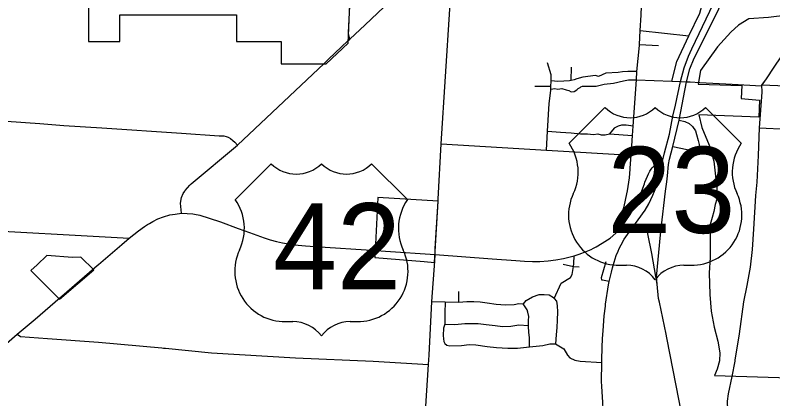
# Model space of a CAD drawing. Extents: x 1729596 to 1925846, y 659247 to 911751.
# Drawn here: x 1799698 to 1811952, y 827504 to 833706 of the extents above; entities that cross this region are included whole.
import ezdxf

# ---------------------------------------------------------------- set-up
doc = ezdxf.new("R2010")
doc.units = 0
for name, color, linetype in [('GM_X_City_Street', 7, 'Continuous'), ('GM_X_Corporation', 7, 'Continuous'), ('GM_X_County_Road', 7, 'Continuous'), ('GM_X_Township_Road', 7, 'Continuous'), ('GM_X_US_Route', 7, 'Continuous'), ('GM_X_US_Shield', 7, 'Continuous')]:
    doc.layers.add(name, color=color, linetype=linetype)

msp = doc.modelspace()

# ---------------------------------------------------------------- linework, layer by layer
at = {"layer": 'GM_X_City_Street'}
for points in [[(1810317, 832639), (1810397, 832959), (1810594, 833371), (1810771, 833738), (1810817, 833894), (1810835, 834363), (1810894, 835206), (1810935, 835731), (1810971, 836241), (1810972, 836258)], [(1809820, 833706), (1809822, 833736), (1809864, 834413), (1809877, 834634), (1809916, 835275), (1809958, 835900), (1809966, 836004), (1809968, 836028), (1809972, 836063)], [(1810558, 832630), (1810609, 832836), (1810677, 833010), (1810904, 833460), (1811253, 834162), (1811728, 835119), (1811786, 835192), (1811850, 835258), (1811945, 835287)], [(1805078, 833290), (1805108, 833319), (1805356, 833551), (1805763, 833930), (1806341, 834474), (1806704, 834818), (1806800, 834898), (1806981, 834892), (1807110, 834884), (1807396, 834863), (1807615, 834857), (1807685, 834849), (1807777, 834831), (1808186, 834806), (1808431, 834743), (1809378, 834672), (1809877, 834634)], [(1806587, 831627), (1806800, 834898)], [(1809670, 831595), (1809681, 831762), (1809691, 831914), (1809749, 832662), (1809755, 832796), (1809793, 833217), (1809794, 833230), (1809804, 833457), (1809820, 833706)], [(1809804, 833457), (1810594, 833371)], [(1809794, 833230), (1810103, 833214)], [(1802546, 830982), (1802546, 830982), (1803292, 831607), (1804693, 832927), (1804742, 832975), (1804765, 832997)], [(1808363, 832536), (1808364, 832559), (1808367, 832634), (1808367, 832642), (1808366, 832740), (1808308, 832933)], [(1808690, 832650), (1808696, 832864)], [(1809755, 832796), (1809609, 832796), (1809520, 832790), (1809449, 832781), (1809253, 832770), (1809131, 832716), (1809086, 832731), (1808880, 832706), (1808780, 832675), (1808737, 832660), (1808690, 832650), (1808661, 832644), (1808569, 832637), (1808475, 832636), (1808367, 832642)], [(1808362, 832511), (1808424, 832523), (1808474, 832510), (1808538, 832518), (1808608, 832499), (1808654, 832486), (1808691, 832468), (1808739, 832473), (1808784, 832497), (1808804, 832521), (1808836, 832536), (1808848, 832546), (1808872, 832556), (1809092, 832556), (1809225, 832590), (1809374, 832609), (1809534, 832644), (1809566, 832648), (1809618, 832659), (1809749, 832662)], [(1809749, 832662), (1810317, 832639), (1810458, 832634), (1810558, 832630), (1810592, 832629), (1810615, 832627)], [(1810283, 831379), (1810333, 831585), (1810436, 832008), (1810558, 832630)], [(1810615, 832627), (1810772, 832619)], [(1808100, 832561), (1808364, 832559)], [(1808294, 831524), (1808309, 831829), (1808309, 831832), (1808337, 832279), (1808362, 832489), (1808362, 832511), (1808363, 832521), (1808363, 832536)], [(1799244, 832014), (1800095, 831955), (1800485, 831925), (1801101, 831884), (1802386, 831797), (1802997, 831758), (1803072, 831753), (1803111, 831746), (1803145, 831733), (1803179, 831713), (1803219, 831680), (1803250, 831653), (1803292, 831607)], [(1810436, 832008), (1810527, 831985), (1810597, 831954), (1810654, 831904), (1810699, 831836), (1810716, 831775), (1810743, 831678), (1810763, 831614), (1810769, 831491)], [(1808309, 831832), (1808519, 831816), (1808689, 831802), (1808840, 831787), (1808952, 831788), (1809052, 831778), (1809122, 831786), (1809178, 831773), (1809238, 831774), (1809310, 831790)], [(1809691, 831914), (1809580, 831927), (1809506, 831928), (1809450, 831914), (1809387, 831881), (1809310, 831790)], [(1809310, 831790), (1809681, 831762), (1809686, 831761)], [(1806541, 830731), (1806587, 831627)], [(1806587, 831627), (1808294, 831524), (1809660, 831441)], [(1809646, 831231), (1809660, 831441), (1809670, 831595)], [(1810333, 831585), (1810769, 831491)], [(1810506, 827220), (1810502, 827229), (1810482, 827281), (1810461, 827356), (1810438, 827474), (1810238, 828490), (1810225, 828549), (1810117, 829066), (1810105, 829126), (1810080, 829357), (1810068, 829471), (1810135, 830154), (1810144, 830257), (1810215, 830861), (1810235, 831013), (1810251, 831109), (1810267, 831292), (1810283, 831379)], [(1809633, 831074), (1809644, 831214), (1809646, 831231)], [(1802440, 830862), (1802445, 830869), (1802525, 830958), (1802546, 830982)], [(1809570, 830713), (1809577, 830741), (1809602, 830864), (1809633, 831074)], [(1802390, 830503), (1802373, 830668), (1802386, 830760), (1802415, 830824), (1802440, 830862)], [(1809566, 830286), (1809560, 830296), (1809544, 830335), (1809522, 830417), (1809520, 830478), (1809528, 830550), (1809545, 830611), (1809570, 830713)], [(1797010, 830375), (1797016, 830374), (1798754, 830257), (1798814, 830253), (1801541, 830101)], [(1809626, 830197), (1809590, 830248), (1809566, 830286)], [(1808732, 829692), (1808741, 829816)], [(1810080, 829357), (1809995, 829854)], [(1806208, 824940), (1806284, 826252), (1806292, 826406), (1806341, 827386), (1806384, 828059), (1806393, 828209), (1806439, 829079), (1806485, 829730)], [(1808416, 829127), (1808530, 829374), (1808678, 829466), (1808707, 829512), (1808728, 829643), (1808732, 829692)], [(1808562, 829683), (1808728, 829643), (1808822, 829637)], [(1809198, 829421), (1809185, 829423), (1809182, 829467), (1809256, 829722)], [(1809303, 829401), (1809198, 829421)], [(1806439, 829079), (1806654, 829072), (1806872, 829066), (1807005, 829076), (1807115, 829079), (1807217, 829073), (1807330, 829057), (1807476, 829033), (1807629, 829022), (1807768, 829031), (1807845, 829047), (1807913, 829041), (1807918, 829041), (1807962, 829095), (1808063, 829150), (1808173, 829189), (1808253, 829190), (1808335, 829183), (1808405, 829142), (1808416, 829127), (1808452, 829081), (1808463, 829005), (1808470, 828909), (1808465, 828773), (1808456, 828658), (1808445, 828536), (1808437, 828393)], [(1806872, 829066), (1806871, 829237)], [(1806654, 829072), (1806648, 828890), (1806647, 828710), (1806624, 828648), (1806622, 828528), (1806623, 828472), (1806630, 828431), (1806646, 828399), (1806678, 828373), (1806729, 828362), (1806918, 828367), (1807039, 828381), (1807150, 828379), (1807331, 828350), (1807483, 828332), (1807666, 828321), (1807825, 828325), (1808016, 828346), (1808231, 828367), (1808345, 828393), (1808437, 828393), (1808573, 828313), (1808630, 828211), (1808668, 828169), (1808748, 828131), (1808837, 828112), (1809185, 828089)], [(1808016, 828346), (1808014, 828493), (1808007, 828577), (1808002, 828679), (1808002, 828689), (1807999, 828770), (1808006, 828834), (1807990, 828904), (1807981, 828942), (1807913, 829041)], [(1806647, 828710), (1806807, 828708), (1806968, 828719), (1807059, 828719), (1807184, 828720), (1807318, 828708), (1807459, 828688), (1807578, 828673), (1807715, 828680), (1807842, 828698), (1808002, 828689)], [(1799732, 828551), (1799782, 828511), (1800219, 828478), (1801044, 828418), (1802068, 828327), (1802099, 828324), (1802131, 828321)], [(1802131, 828321), (1802871, 828248), (1804230, 828165), (1805488, 828115), (1806384, 828059)], [(1811339, 828131), (1811336, 828114), (1811291, 827864), (1811232, 827586), (1811211, 827467), (1811213, 827409), (1811226, 827353), (1811276, 827254), (1811353, 827144), (1811508, 826935), (1811666, 826747), (1811796, 826596), (1811839, 826549), (1811877, 826439), (1812017, 825974), (1812059, 825816)]]:
    msp.add_lwpolyline(points, dxfattribs=at)
at = {"layer": 'GM_X_Corporation'}
for points in [[(1804001, 833279), (1804001, 832917), (1804726, 832917), (1805086, 833256), (1805109, 833878), (1805119, 834238), (1805156, 834964), (1804862, 834990), (1804710, 835001), (1804706, 834830), (1804606, 834832), (1804609, 834963), (1804539, 834967), (1804537, 834834), (1804392, 834837), (1804386, 834576), (1804176, 834580), (1804188, 835155), (1800883, 834212), (1800884, 833279), (1801391, 833279), (1801391, 833714), (1803276, 833714), (1803276, 833279)], [(1805516, 829788), (1806315, 829723), (1806482, 829710), (1806539, 830701), (1805565, 830760)], [(1800052, 829671), (1799954, 829576), (1800416, 829114), (1800968, 829587), (1800758, 829796), (1800625, 829787), (1800210, 829823)]]:
    msp.add_lwpolyline(points, close=True, dxfattribs=at)
for points in [[(1812189, 833704), (1811881, 833666), (1811566, 833646), (1811397, 833543), (1811273, 833433), (1811057, 833195), (1810780, 832810), (1810743, 832591), (1811450, 832568), (1811442, 832360), (1811738, 832332), (1811727, 832058), (1810753, 832094), (1810804, 831891), (1810920, 831606), (1810996, 831345), (1811047, 830907), (1811046, 830734), (1811021, 830645), (1811000, 830534), (1810970, 830437), (1810937, 830321), (1810936, 829787), (1810922, 829539), (1810934, 829192), (1810954, 828923), (1811004, 828664), (1811064, 828438), (1811096, 828247), (1811090, 828117), (1811049, 827984), (1811009, 827882), (1815869, 827729)], [(1813853, 832491), (1811776, 832575), (1811850, 832675), (1811974, 832866)]]:
    msp.add_lwpolyline(points, dxfattribs=at)
at = {"layer": 'GM_X_County_Road'}
for points in [[(1804765, 832997), (1805078, 833290)], [(1806485, 829730), (1806492, 829835), (1806493, 829933), (1806539, 830701), (1806541, 830731)], [(1809930, 830171), (1809919, 830224)], [(1809995, 829854), (1809930, 830171), (1809930, 830171)]]:
    msp.add_lwpolyline(points, dxfattribs=at)
at = {"layer": 'GM_X_Township_Road'}
for points in [[(1805108, 833319), (1805089, 833401), (1805087, 833427), (1805166, 834925), (1805165, 834959), (1805157, 834980), (1805149, 834992), (1805142, 834997)], [(1811766, 832565), (1811850, 832675), (1811974, 832866), (1812189, 833183), (1812337, 833398), (1812457, 833548)], [(1810772, 832619), (1811295, 832591)], [(1811295, 832591), (1811766, 832565), (1811773, 832475), (1811772, 832461)], [(1811772, 832461), (1811732, 831884), (1811714, 831436), (1811691, 831009), (1811673, 830792), (1811638, 830245), (1811618, 829920), (1811585, 829634), (1811531, 829335), (1811480, 829070), (1811410, 828555), (1811339, 828131)], [(1811732, 831884), (1812190, 831865), (1812461, 831851), (1813734, 831797), (1813810, 831792), (1815017, 831728), (1815419, 831700), (1815762, 831691), (1815839, 831685)]]:
    msp.add_lwpolyline(points, dxfattribs=at)
at = {"layer": 'GM_X_US_Route'}
for points in [[(1810375, 832252), (1810458, 832634), (1810519, 832855), (1810590, 833042), (1810642, 833161), (1810931, 833769), (1811145, 834201), (1811545, 835017), (1811721, 835387), (1811810, 835583), (1811858, 835709), (1811904, 835901), (1811923, 836046), (1811940, 836302), (1811943, 836419), (1811905, 836674), (1811861, 836825), (1811798, 837006), (1811769, 837090), (1811671, 837289), (1811535, 837559), (1811464, 837713)], [(1810200, 831481), (1810278, 831782), (1810336, 832074), (1810375, 832252)], [(1810161, 831327), (1810200, 831481)], [(1809658, 830240), (1809887, 830554), (1809944, 830656), (1810013, 830794), (1810064, 830924), (1810114, 831096), (1810123, 831139), (1810161, 831327)], [(1809806, 830793), (1809817, 830824), (1809875, 830980), (1809883, 831007), (1809924, 831101), (1809942, 831139), (1809965, 831182), (1809982, 831214), (1810002, 831240), (1810018, 831255)], [(1810018, 831255), (1810029, 831264), (1810062, 831287), (1810099, 831310), (1810129, 831322), (1810161, 831327)], [(1809565, 830366), (1809645, 830481), (1809731, 830633), (1809791, 830753), (1809806, 830793)], [(1801840, 830321), (1801868, 830339), (1801922, 830372), (1802008, 830412), (1802096, 830448), (1802197, 830477), (1802286, 830491), (1802390, 830503), (1802479, 830501), (1802573, 830493), (1802598, 830488)], [(1802598, 830488), (1802682, 830472), (1802838, 830425), (1803021, 830363), (1803306, 830259), (1803490, 830195), (1803724, 830107), (1803823, 830072), (1803927, 830046), (1804023, 830024), (1804119, 830008), (1804217, 829996), (1804391, 829979), (1804546, 829967), (1805540, 829901)], [(1809054, 829941), (1809092, 829962), (1809190, 830018), (1809319, 830101), (1809414, 830184), (1809493, 830273), (1809544, 830335), (1809565, 830366)], [(1801541, 830101), (1801693, 830220), (1801792, 830288), (1801840, 830321)], [(1809448, 829889), (1809465, 829932), (1809500, 829994), (1809550, 830083), (1809626, 830197), (1809658, 830240)], [(1801022, 829657), (1801044, 829677), (1801421, 829999)], [(1801421, 829999), (1801541, 830101)], [(1805540, 829901), (1805687, 829891), (1806492, 829835)], [(1806492, 829835), (1807414, 829767), (1807797, 829742), (1807937, 829731), (1808063, 829726), (1808184, 829726), (1808317, 829734), (1808441, 829749), (1808567, 829774), (1808741, 829816), (1808822, 829845), (1808931, 829885), (1809015, 829920), (1809054, 829941)], [(1809341, 829549), (1809360, 829624), (1809385, 829713), (1809419, 829819), (1809448, 829889)], [(1800425, 829142), (1800450, 829164), (1801022, 829657)], [(1809303, 829401), (1809341, 829549)], [(1809295, 829348), (1809303, 829401)], [(1809248, 829033), (1809295, 829348)], [(1797621, 826760), (1797666, 826798), (1798064, 827135), (1798491, 827497), (1799248, 828136), (1799732, 828551), (1800024, 828792), (1800425, 829142)], [(1809185, 828132), (1809189, 828331), (1809196, 828477), (1809207, 828601), (1809226, 828846), (1809244, 829004), (1809248, 829033)], [(1809185, 827707), (1809181, 827785), (1809185, 828089), (1809185, 828132)], [(1809214, 827282), (1809209, 827339), (1809200, 827447), (1809185, 827707)]]:
    msp.add_lwpolyline(points, dxfattribs=at)
at = {"layer": 'GM_X_US_Shield'}
for p, q in [((1809237, 832215), (1808657, 831635)), ((1809237, 832215), (1808657, 831635)), ((1811442, 831635), (1810862, 832215)), ((1811442, 831635), (1810862, 832215)), ((1803839, 831304), (1803259, 830724)), ((1803839, 831304), (1803259, 830724)), ((1806043, 830724), (1805463, 831304)), ((1806043, 830724), (1805463, 831304)), ((1809469, 829663), (1809586, 829663)), ((1809469, 829663), (1809586, 829663)), ((1810514, 829663), (1810630, 829663)), ((1810514, 829663), (1810630, 829663)), ((1804071, 828752), (1804187, 828752)), ((1804071, 828752), (1804187, 828752)), ((1805115, 828752), (1805231, 828752)), ((1805115, 828752), (1805231, 828752))]:
    msp.add_line(p, q, dxfattribs=at)
for centre, radius, start, end in [((1809644, 832629), 580, 225.573, 314.427), ((1809644, 832629), 580, 225.573, 314.427), ((1810456, 832629), 580, 225.573, 314.427), ((1810456, 832629), 580, 225.573, 314.427), ((1807992, 831169), 812, 334.5471, 35.0009), ((1807992, 831169), 812, 334.5471, 35.0009), ((1812107, 831169), 812, 144.9991, 205.4529), ((1812107, 831169), 812, 144.9991, 205.4529), ((1804245, 831718), 580, 225.573, 314.427), ((1804245, 831718), 580, 225.573, 314.427), ((1805057, 831718), 580, 225.573, 314.427), ((1805057, 831718), 580, 225.573, 314.427), ((1802593, 830258), 812, 334.5471, 35.0009), ((1802593, 830258), 812, 334.5471, 35.0009), ((1806708, 830258), 812, 144.9991, 205.4529), ((1806708, 830258), 812, 144.9991, 205.4529), ((1809460, 830475), 812, 154.8319, 270.6383), ((1809460, 830475), 812, 154.8319, 270.6383), ((1810639, 830475), 812, 269.3617, 25.1681), ((1810639, 830475), 812, 269.3617, 25.1681), ((1804062, 829564), 812, 154.8319, 270.6383), ((1804062, 829564), 812, 154.8319, 270.6383), ((1805240, 829564), 812, 269.3617, 25.1681), ((1805240, 829564), 812, 269.3617, 25.1681), ((1809586, 829082), 580, 36.8699, 90), ((1809586, 829082), 580, 36.8699, 90), ((1810514, 829082), 580, 90, 143.1301), ((1810514, 829082), 580, 90, 143.1301), ((1804187, 828172), 580, 36.8699, 90), ((1804187, 828172), 580, 36.8699, 90), ((1805115, 828172), 580, 90, 143.1301), ((1805115, 828172), 580, 90, 143.1301)]:
    msp.add_arc(centre, radius, start, end, dxfattribs=at)

# ---------------------------------------------------------------- texts
for s, p in [('23', (1809275, 830185)), ('23', (1809275, 830185)), ('42', (1803867, 829274)), ('42', (1803867, 829274))]:
    msp.add_text(s, height=1392.2, dxfattribs=at).set_placement(p)

doc.saveas('drawing.dxf')
